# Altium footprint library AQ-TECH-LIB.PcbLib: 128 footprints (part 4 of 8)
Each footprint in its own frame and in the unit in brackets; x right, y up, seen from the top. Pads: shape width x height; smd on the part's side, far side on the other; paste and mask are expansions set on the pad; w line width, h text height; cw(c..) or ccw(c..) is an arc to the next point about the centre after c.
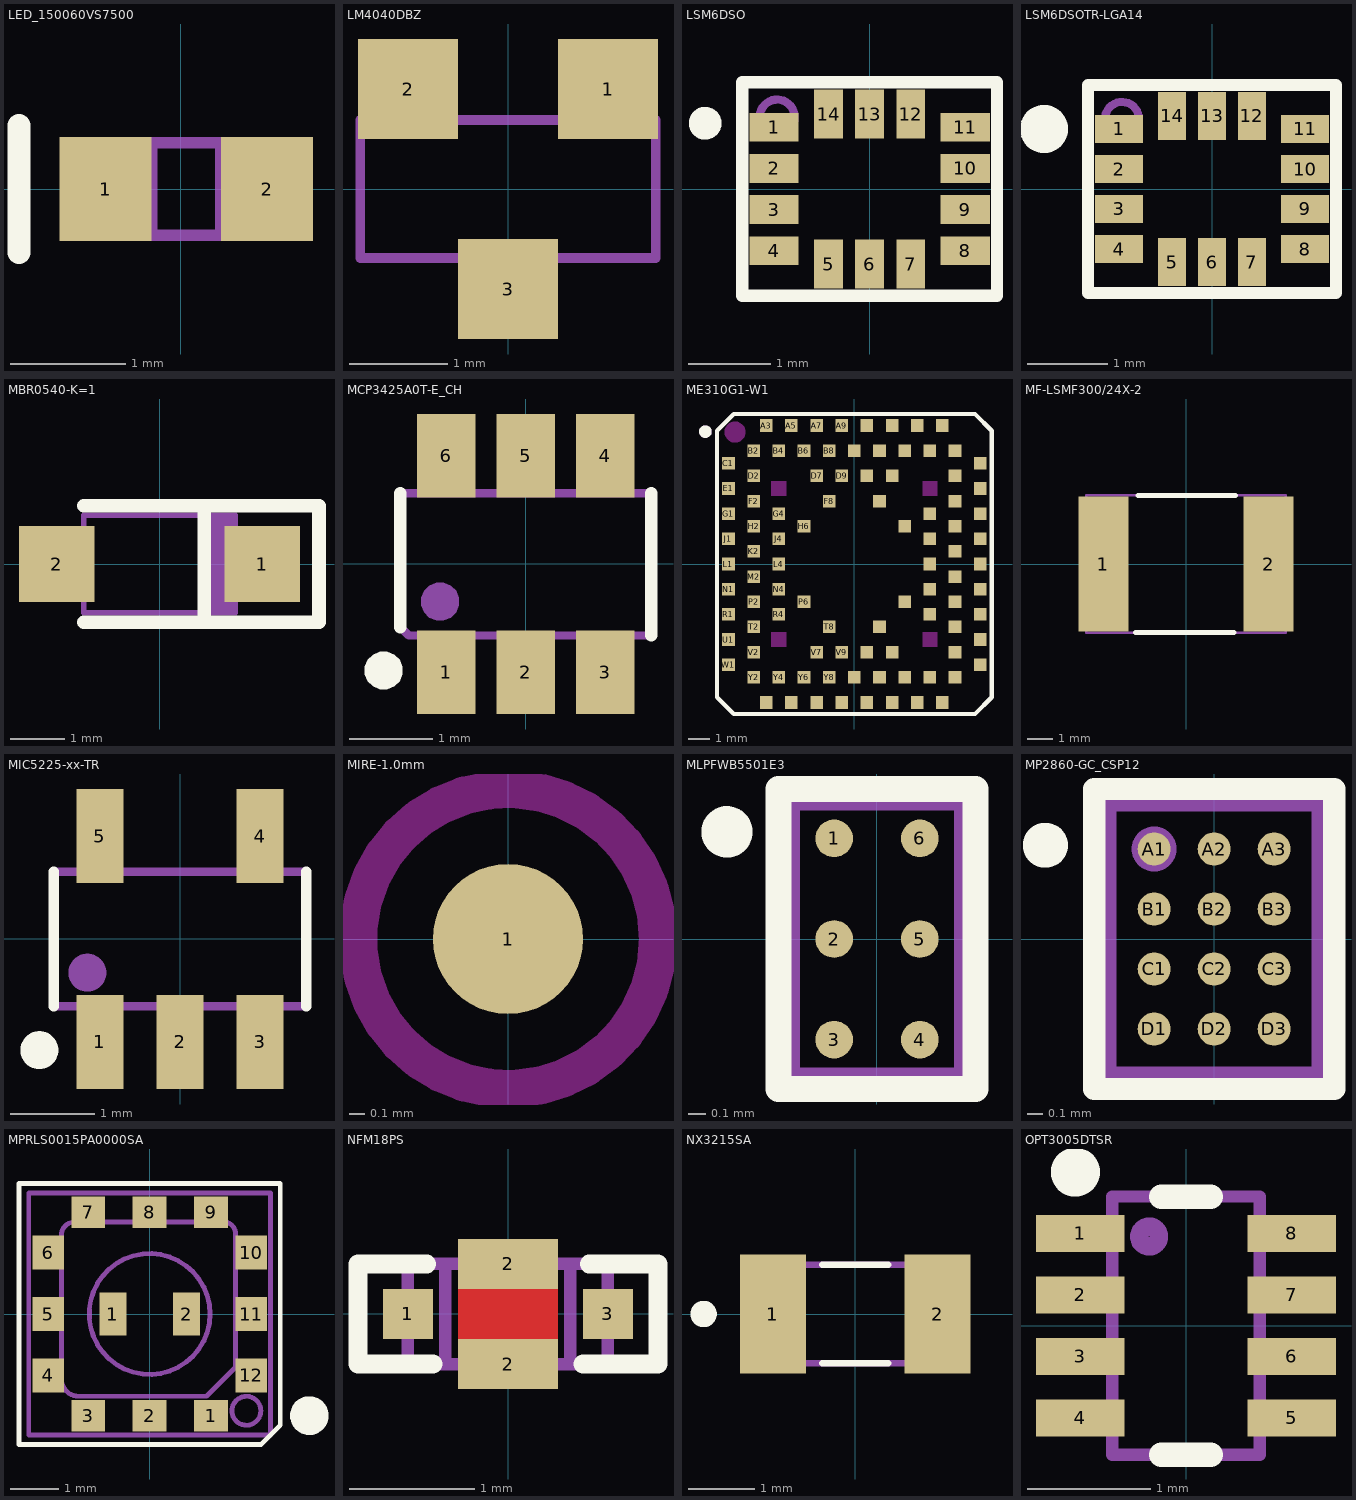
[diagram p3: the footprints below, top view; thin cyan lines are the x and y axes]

## LED_150060VS7500 [mm]
height 0.8
pads (2):
  rect 0.8x0.9 smd: 1(-0.65,0) 2(0.75,0)
Top Overlay:
  lines w0.2: -1.4,-0.55 -1.4,0.55
Mechanical 3:
  circle w0.1: c-0.5,-0.175 r0.1
  lines w0.1: -0.25,-0.4 -0.25,0.4 ; 0.35,-0.4 0.35,0.4 ; -0.75,-0.4 -0.75,0.4 0.85,0.4 0.85,-0.4 -0.75,-0.4
  text ".Designator" at -1.125,0.625 h0.84
  text "K" at -1.15,-0.2 h0.42
3D body "STP_150060xS75000 (rev1).stp": height 0.7, standoff 0, extent -0.75,-0.4 0.85,0.4

## LM4040DBZ [mil]
height 44.09
pads (3):
  rect 40x40 smd: 1(40,40) 2(-40,40) 3(0,-40)
Mechanical 3:
  lines w3.94: -59.1,-27.6 -59.1,27.6 -47,27.6 -47,49.2 -28,49.2 -28,27.6 28,27.6 28,49.2 47,49.2 47,27.6 59.1,27.6 59.1,-27.6 9.5,-27.6 9.5,-49.2 -9.5,-49.2 -9.5,-27.6 -59.1,-27.6
  text ".Designator" at -28,-21.65 h33.07
3D body "Conception1.stp": height 43.31, standoff 0, extent -59.05,-49.21 59.06,49.22

## LSM6DSO [mm]
height 0.86
pads (14):
  rect 0.6x0.35 smd paste+0 mask+0: 1(-1.162,0.75) 2(-1.162,0.25) 3(-1.162,-0.25) 4(-1.162,-0.75) 8(1.162,-0.75) 9(1.162,-0.25) 10(1.162,0.25) 11(1.162,0.75)
  rect 0.35x0.6 smd paste+0 mask+0: 5(-0.5,-0.913) 6(0,-0.913) 7(0.5,-0.913) 12(0.5,0.913) 13(0,0.913) 14(-0.5,0.913)
Top Overlay:
  circle w0.2: c-2,0.8 r0.1
  lines w0.15: -1.55,-1.3 -1.55,1.3 1.55,1.3 1.55,-1.3 -1.55,-1.3
Mechanical 3:
  circle w0.1: c-1.125,0.875 r0.213
  lines w0.1: -1.55,-1.3 1.55,-1.3 1.55,1.3 -1.55,1.3 -1.55,-1.3
  text "'.Designator'" at -1.162,-0.25 h1
3D body: height 0.87, standoff 0, extent -1.374,0.625 -0.876,1.125
3D body: height 0.86, standoff 0, extent -1.55,-1.3 1.55,1.3

## LSM6DSOTR-LGA14 [mm] "2.5X3.0X0.86"
height 0.86
pads (14):
  rect 0.6x0.35 smd mask+0.025: 1(-1.162,0.75) 2(-1.162,0.25) 3(-1.162,-0.25) 4(-1.162,-0.75) 8(1.162,-0.75) 9(1.162,-0.25) 10(1.162,0.25) 11(1.162,0.75)
  rect 0.35x0.6 smd mask+0.025: 5(-0.5,-0.913) 6(0,-0.913) 7(0.5,-0.913) 12(0.5,0.913) 13(0,0.913) 14(-0.5,0.913)
Top Overlay:
  circle w0.4: c-2.1,0.75 r0.1
  lines w0.15: -1.55,-1.3 1.55,-1.3 1.55,1.3 -1.55,1.3 -1.55,-1.3
Mechanical 3:
  circle w0.1: c-1.125,0.875 r0.213
  lines w0.1: -1.55,-1.3 -1.55,1.3 1.55,1.3 1.55,-1.3 -1.55,-1.3
  text "'.Designator'" at 0.7,0.3 h0.6
3D body: height 0.86, standoff 0, extent -1.55,-1.3 1.55,1.3
3D body: height 0.87, standoff 0, extent -1.374,0.625 -0.876,1.125

## MBR0540-K=1 [mm]
height 1.28
pads (2):
  rect 1.4x1.4 smd paste+0 mask+0.1: 1(1.9,0) 2(-1.9,0)
Top Overlay:
  lines w0.25: -1.4,-1.075 2.95,-1.075 2.95,-0.25 ; -1.4,1.075 2.95,1.075 2.95,-0.25 ; 0.825,-1 0.825,1 ; 2.95,-0.25 2.95,-0.25
Mechanical 3:
  region: 1.4,0.9 0.8,0.9 0.8,-0.9 1.4,-0.9
  lines w0.1: -1.9,-0.3 -1.4,-0.3 -1.4,0.3 -1.9,0.3 -1.9,-0.3 ; -1.4,-0.9 -1.4,0.9 1.4,0.9 1.4,-0.9 -1.4,-0.9 ; 1.4,-0.3 1.9,-0.3 1.9,0.3 1.4,0.3 1.4,-0.3
  text ".Designator" at -0.8,-0.265 h0.6
3D body "SOD123(refusion).stp": height 1.28, standoff 0, extent -1.85,-0.8 1.85,0.8

## MCP3425A0T-E_CH [mm] "refusion"
height 1.45
pads (6):
  rect 0.7x1 smd paste+0 mask+0.05: 1(-0.95,-1.295) 2(0,-1.295) 3(0.95,-1.295) 4(0.95,1.295) 5(0,1.295) 6(-0.95,1.295)
Top Overlay:
  region: -1.7,-1.5 -1.745,-1.5 -1.827,-1.466 -1.891,-1.402 -1.925,-1.32 -1.925,-1.23 -1.891,-1.148 -1.827,-1.084 -1.745,-1.05 -1.7,-1.05 -1.655,-1.05 -1.573,-1.084 -1.509,-1.148 -1.475,-1.23 -1.475,-1.32 -1.509,-1.402 -1.573,-1.466 -1.655,-1.5
  lines w0.15: -1.5,-0.755 -1.5,0.845 ; 1.5,-0.855 1.5,0.845
Mechanical 3:
  region: -1.025,-0.675 -1.07,-0.675 -1.152,-0.641 -1.216,-0.577 -1.25,-0.495 -1.25,-0.405 -1.216,-0.323 -1.152,-0.259 -1.07,-0.225 -1.025,-0.225 -0.98,-0.225 -0.898,-0.259 -0.834,-0.323 -0.8,-0.405 -0.8,-0.495 -0.834,-0.577 -0.898,-0.641 -0.98,-0.675
  lines w0.1: -1.5,-0.755 -1.4,-0.855 1.5,-0.855 1.5,0.845 -1.5,0.845 -1.5,-0.755
  text ".Designator" at 0,0 h1
3D body "SOT23-6(refusion).stp": height 1.45, standoff 0, extent -1.5,-1.5 1.5,1.5

## ME310G1-W1 [mm]
height 2.6
pads (94):
  rect 0.6x0.6 smd mask+0.1: A3(-4.2,6.6) A5(-3,6.6) A7(-1.8,6.6) A9(-0.6,6.6) A11(0.6,6.6) A13(1.8,6.6) A15(3,6.6) A17(4.2,6.6) AA3(-4.2,-6.6) AA5(-3,-6.6) AA7(-1.8,-6.6) AA9(-0.6,-6.6) AA11(0.6,-6.6) AA13(1.8,-6.6) AA15(3,-6.6) AA17(4.2,-6.6) B2(-4.8,5.4) B4(-3.6,5.4) B6(-2.4,5.4) B8(-1.2,5.4) B10(0,5.4) B12(1.2,5.4) B14(2.4,5.4) B16(3.6,5.4) B18(4.8,5.4) C1(-6,4.8) C19(6,4.8) D2(-4.8,4.2) D7(-1.8,4.2) D9(-0.6,4.2) D11(0.6,4.2) D13(1.8,4.2) D18(4.8,4.2) E1(-6,3.6) E19(6,3.6) F2(-4.8,3) F8(-1.2,3) F12(1.2,3) F18(4.8,3) G1(-6,2.4) G4(-3.6,2.4) G16(3.6,2.4) G19(6,2.4) H2(-4.8,1.8) H6(-2.4,1.8) H14(2.4,1.8) H18(4.8,1.8) J1(-6,1.2) J4(-3.6,1.2) J16(3.6,1.2) J19(6,1.2) K2(-4.8,0.6) K18(4.8,0.6) L1(-6,0) L4(-3.6,0) L16(3.6,0) L19(6,0) M2(-4.8,-0.6) M18(4.8,-0.6) N1(-6,-1.2) N4(-3.6,-1.2) N16(3.6,-1.2) N19(6,-1.2) P2(-4.8,-1.8) P6(-2.4,-1.8) P14(2.4,-1.8) P18(4.8,-1.8) R1(-6,-2.4) R4(-3.6,-2.4) R16(3.6,-2.4) R19(6,-2.4) T2(-4.8,-3) T8(-1.2,-3) T12(1.2,-3) T18(4.8,-3) U1(-6,-3.6) U19(6,-3.6) V2(-4.8,-4.2) V7(-1.8,-4.2) V9(-0.6,-4.2) V11(0.6,-4.2) V13(1.8,-4.2) V18(4.8,-4.2) W1(-6,-4.8) W19(6,-4.8) Y2(-4.8,-5.4) Y4(-3.6,-5.4) Y6(-2.4,-5.4) Y8(-1.2,-5.4) Y10(0,-5.4) Y12(1.2,-5.4) Y14(2.4,-5.4) Y16(3.6,-5.4) Y18(4.8,-5.4)
Top Layer keep-out:
  circle w0.5: c-5.69,6.29 r0.25
  region: -3.25,-3.95 -3.95,-3.95 -3.95,-3.25 -3.25,-3.25
  region: -3.25,3.25 -3.95,3.25 -3.95,3.95 -3.25,3.95
  region: 3.95,3.25 3.25,3.25 3.25,3.95 3.95,3.95
  region: 3.95,-3.95 3.25,-3.95 3.25,-3.25 3.95,-3.25
Top Overlay:
  circle w0.3: c-7.1,6.31 r0.15
  lines w0.2: -6.55,-6.35 -5.75,-7.15 5.75,-7.15 6.55,-6.35 6.55,6.35 5.75,7.15 -5.75,7.15 -6.55,6.35 -6.55,-6.35
Mechanical 3:
  circle w0.3: c-7.1,6.31 r0.15
  lines w0.1: -6.55,-6.35 -6.55,6.35 -5.75,7.15 5.75,7.15 6.55,6.35 6.55,-6.35 5.75,-7.15 -5.75,-7.15 -6.55,-6.35
  text ".Designator" at -0.025,-0.075 h0.84
3D body "step_temp.STEP": height 2.6, standoff 0, extent -6.55,-7.15 6.55,7.15

## MF-LSMF300/24X-2 [mm] "FUSE"
height 1.6
pads (2):
  rect 2x5.4 smd paste+0 mask+0.1: 1(-3.3,0) 2(3.3,0)
Top Overlay:
  lines w0.2: -2.025,-2.75 1.925,-2.75 ; -1.925,2.75 1.975,2.75
Mechanical 3:
  lines w0.1: -4,-2.75 -4,2.75 4,2.75 4,-2.75 -4,-2.75
  text "'.Designator'" at 0,0 h1
3D body: height 1.6, standoff 0, extent -4,-2.75 4,2.75

## MIC5225-xx-TR [mil] "refusion"
height 57.09
pads (5):
  rect 22x44 smd paste+0 mask+3.94: 1(-37.4,-48.11) 2(0,-48.11) 3(37.4,-48.11) 4(37.4,48.11) 5(-37.4,48.11)
Top Overlay:
  lines w4.92: -59.06,-31.5 -59.06,31.5 ; 59.06,-31.5 59.06,31.5
  lines w9.84: -65.75,-55.91 ccw(c-65.75,-51.97) -65.75,-48.03 ccw(c-65.75,-51.97) -65.75,-55.91
Mechanical 3:
  lines w3.94: -59.06,-31.5 -59.06,31.5 59.06,31.5 59.06,-31.5 -59.06,-31.5
  lines w9.84: -43.31,-19.68 cw(c-43.31,-15.75) -43.31,-11.81 cw(c-43.31,-15.75) -43.31,-19.68
  text ".Designator" at -54.08,-9.65 h33.07
3D body "sot23-5.stp": height 43.31, standoff 0, extent -59.05,-49.2 59.06,49.22

## MIRE-1.0mm [mm] "refusion"
height 11.5
pads (1):
  round 1 smd paste+0 mask+0.5: 1(0,0)
Top Layer keep-out:
  circle w0.254: c0,0 r1

## MLPFWB5501E3 [mm]
height 0.4
pads (6):
  round 0.22 smd mask+0.04: 1(-0.25,0.587) 2(-0.25,0) 3(-0.25,-0.587) 4(0.25,-0.587) 5(0.25,0) 6(0.25,0.587)
Top Overlay:
  circle w0.2: c-0.875,0.625 r0.05
  lines w0.15: -0.575,-0.875 -0.575,0.875 0.575,0.875 0.575,-0.875 -0.575,-0.875
Mechanical 3:
  lines w0.1: -0.5,-0.8 0.5,-0.8 0.5,0.8 -0.5,0.8 -0.5,-0.8
  text "GND" at 0.05,-0.65 h0.2
  text "GND" at 0.05,-0.05 h0.2
  text "GND" at -0.425,-0.05 h0.2
  text "GND" at 0.05,0.525 h0.2
  text "IN" at -0.375,-0.65 h0.2
  text "OUT" at -0.425,0.375 h0.2
  text "'.Designator'" at 0.05,-0.75 h0.6
3D body: height 0.4, standoff 0, extent -0.5,-0.8 0.5,0.8
3D body: height 0.4, standoff 0, extent -0.349,0.475 -0.15,0.675

## MP2860-GC_CSP12 [mm] "1.4x1.8MM PAS 0.4MM"
height 0.63
pads (12):
  round 0.22 smd mask+0.04: A1(-0.4,0.6) A2(0,0.6) A3(0.4,0.6) B1(-0.4,0.2) B2(0,0.2) B3(0.4,0.2) C1(-0.4,-0.2) C2(0,-0.2) C3(0.4,-0.2) D1(-0.4,-0.6) D2(0,-0.6) D3(0.4,-0.6)
Top Overlay:
  circle w0.2: c-1.125,0.625 r0.05
  lines w0.15: -0.8,-1 -0.8,1 0.8,1 0.8,-1 -0.8,-1
Mechanical 3:
  circle w0.2: c-0.4,0.6 r0.05
  lines w0.1: -0.7,-0.9 0.7,-0.9 0.7,0.9 -0.7,0.9 -0.7,-0.9
  text "1" at -0.7,0.9 h0.4
  text "A" at -1.125,0.425 h0.4
  text "D" at -1.125,-0.875 h0.4
  text "3" at 0.288,0.9 h0.4
  text "'.Designator'" at 0.284,-0.45 h0.6
3D body: height 0.65, standoff 0, extent -0.7,-0.9 0.7,0.9
3D body: height 0.66, standoff 0, extent -0.5,0.5 -0.3,0.7

## MPRLS0015PA0000SA [mm] "CAPTEUR PRESSION"
height 5.8
pads (14):
  rect 0.559x0.889 smd: 1(-0.762,0) 2(0.762,0)
  rect 0.7x0.65 smd mask+0.028: 1(1.27,-2.1) 3(-1.27,-2.1) 7(-1.27,2.1) 9(1.27,2.1)
  rect 0.7x0.65 smd: 2(0,-2.1) 8(0,2.1)
  rect 0.65x0.7 smd mask+0.028: 4(-2.1,-1.27) 6(-2.1,1.27) 10(2.1,1.27) 12(2.1,-1.27)
  rect 0.65x0.7 smd: 5(-2.1,0) 11(2.1,0)
Top Overlay:
  circle w0.4: c3.3,-2.1 r0.2
  lines w0.1: -2.7,-2.7 -2.7,2.7 2.7,2.7 2.7,-2.3 2.3,-2.7 -2.7,-2.7
Mechanical 3:
  circle w0.1: c0,0 r1.25
  circle w0.1: c1.999,-2 r0.299
  lines w0.1: -1.585,1.9 1.535,1.9 cw(c1.535,1.66) 1.775,1.66 1.775,-1.1 ; -1.555,1.9 ccw(c-1.555,1.63) -1.825,1.63 -1.825,-1.34 ccw(c-1.465,-1.34) -1.465,-1.7 1.175,-1.7 1.775,-1.1 ; 1.775,-1.1 ccw(c1.775,-1.1) 1.775,-1.1 ; -2.5,-2.5 -2.5,2.5 2.5,2.5 2.5,-2.5 -2.5,-2.5
  text "'.Designator'" at -0.754,-0.47 h1
3D body: height 2.2, standoff 0, extent -1.825,-1.7 1.775,1.9
3D body: height 5.8, standoff 0, extent -1.24,-1.247 1.25,1.248
3D body: height 0.6, standoff 0, extent -2.54,-2.537 2.54,2.537
3D body: height 0.61, standoff 0, extent 1.701,-2.299 2.299,-1.701

## NFM18PS [mm]
height 0.7
pads (4):
  rect 0.4x0.4 smd mask+0.05: 1(-0.8,0) 3(0.8,0)
  rect 0.8x0.4 smd mask+0.05: 2(0,-0.4) 2(0,0.4)
Top Layer:
  rectangle: -0.4,-0.6 0.4,0.6
Top Overlay:
  lines w0.15: -0.65,0.4 -1.2,0.4 -1.2,-0.4 -0.6,-0.4 ; 0.6,-0.4 1.2,-0.4 1.2,0.4 0.65,0.4
Mechanical 3:
  lines w0.1: -0.8,-0.4 0.8,-0.4 ; -0.8,-0.4 -0.8,0.4 ; -0.8,-0.4 -0.5,-0.4 -0.5,0.4 -0.8,0.4 ; -0.8,-0.4 -0.8,0.4 ; -0.8,0.4 0.8,0.4 ; 0.8,-0.4 0.8,0.4 ; 0.8,-0.4 0.5,-0.4 0.5,0.4 0.8,0.4 ; 0.8,-0.4 0.8,0.4
  text ".Designator" at 3.45,0.45 h0.84
3D body: height 0.7, standoff 0, extent -0.8,-0.4 0.8,0.4

## NX3215SA [mm]
height 0.9
pads (2):
  rect 1x1.8 smd: 1(-1.25,0) 2(1.25,0)
Top Overlay:
  lines w0.1: -0.5,-0.75 0.5,-0.75 ; -0.5,0.75 0.5,0.75
  lines w0.2: -2.3,-0.1 cw(c-2.3,0) -2.3,0.1 cw(c-2.3,0) -2.3,-0.1
Mechanical 1:
  lines w0.1: -1.6,-0.75 1.6,-0.75 1.6,0.75 -1.6,0.75 -1.6,-0.75
Mechanical 3:
  text ".Designator" at 0,0 h0.84
3D body "NX3215SA-32.768K-EXS00A-MU00003.stp": height 0.8, standoff 0, extent -1.6,-0.75 1.6,0.75

## OPT3005DTSR [mm] "SOT8-5X3MM"
height 0.6
pads (8):
  rect 0.72x0.3 smd mask+0.05: 1(-0.86,0.75) 2(-0.86,0.25) 3(-0.86,-0.25) 4(-0.86,-0.75) 5(0.86,-0.75) 6(0.86,-0.25) 7(0.86,0.25) 8(0.86,0.75)
Top Overlay:
  circle w0.3: c-0.9,1.25 r0.05
  lines w0.2: -0.2,-1.05 0.2,-1.05 ; -0.2,1.05 0.2,1.05
Mechanical 3:
  circle w0.15: c-0.3,0.725 r0.08
  lines w0.1: -0.6,-1.05 -0.6,1.05 0.6,1.05 0.6,-1.05 -0.6,-1.05
3D body "OPT3005DTSR.stp": height 0.7, standoff 0, extent -0.6,-1.05 0.6,1.05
